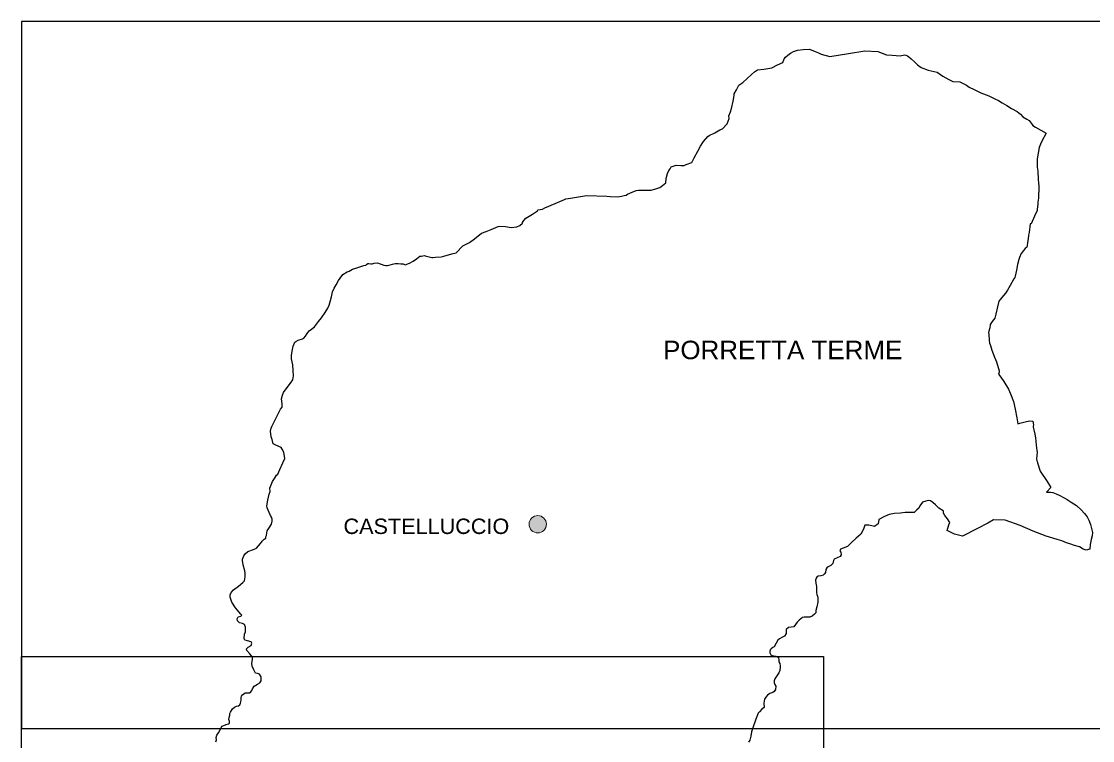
# Model space of a CAD drawing. Extents: x 645880 to 658994, y 884400 to 894744.
# Drawn here: x 646462 to 647332, y 885506 to 886090 of the extents above; entities that cross this region are included whole.
import ezdxf
from ezdxf.enums import TextEntityAlignment as Align

# ---------------------------------------------------------------- set-up
doc = ezdxf.new("R2010")
doc.units = 0
doc.header["$LTSCALE"] = 10
doc.layers.add('63', color=7, linetype='Continuous', lineweight=35)

msp = doc.modelspace()

# ---------------------------------------------------------------- hatches: boundary and pattern name
at = {"layer": '63'}
msp.add_hatch(color=256, dxfattribs=at).paths.add_polyline_path([(646888.14, 885681.98, 1), (646874.05, 885681.98, 1)])

# ---------------------------------------------------------------- linework, layer by layer
at = {"layer": '63', "lineweight": 25}
for points in [[(647342.83, 886090.07), (646461.84, 886090.07), (646461.84, 885516.07), (647342.83, 885516.07)], [(647342.83, 886090.07), (646461.84, 886090.07), (646461.84, 885516.07), (647342.83, 885516.07)], [(647113.21, 885058.94), (646461.84, 885058.94), (646461.84, 885574.51), (647113.21, 885574.51)]]:
    msp.add_lwpolyline(points, close=True, dxfattribs=at)
for points in [[(647034.9, 886007.04), (647036.53, 886011.16), (647036.21, 886013.32), (647037.56, 886016.62), (647038.28, 886019.32), (647039.79, 886025.24), (647040.58, 886029.86), (647040.58, 886031.25), (647042.4, 886034.66), (647044.38, 886038.35), (647047.64, 886040.43), (647054.7, 886047.12), (647057.08, 886049.28), (647059.54, 886050.82), (647064.61, 886051.43), (647069.61, 886052.2), (647071.2, 886052.51), (647075.72, 886054.82), (647080.12, 886056.72), (647081.23, 886059.65), (647082.26, 886061.11), (647084.25, 886062.8), (647086.23, 886064.34), (647088.69, 886065.57), (647092.02, 886066.73), (647096.46, 886067.19), (647101.78, 886067.57), (647106.38, 886065.65), (647108.91, 886064.5), (647111.24, 886063.54), (647118.1, 886061.69), (647133.29, 886063.96), (647146.57, 886066.15), (647157.27, 886065.53), (647164.34, 886062.93), (647168.79, 886062.58), (647175.22, 886062.1), (647178.75, 886062.86), (647180.03, 886062.79), (647181.23, 886062.24)], [(647181.23, 886062.24), (647182.43, 886061.42), (647184.19, 886059.77), (647187.16, 886056.96), (647189.47, 886054.72), (647192.51, 886052.73), (647198.09, 886050.47), (647205.3, 886048.96), (647210.1, 886045.74), (647214.84, 886042.86), (647218.12, 886041.36), (647223.77, 886040.94), (647229.21, 886038.41), (647231.4, 886036.83), (647235.29, 886034.84), (647240.87, 886032.17), (647247.44, 886029.77), (647252.25, 886027.23), (647255.07, 886025.86), (647258.27, 886023.98), (647262.02, 886021.78), (647265.62, 886019.31), (647270.35, 886016.85), (647272.9, 886014.93), (647274.95, 886012.66), (647278.27, 886010.68), (647280.11, 886009.65), (647280.81, 886008.55), (647282.37, 886006.29), (647283.07, 886005.6), (647285.18, 886004.25), (647293.8, 885999.25), (647290.34, 885993.01), (647289.21, 885990.54), (647288.29, 885987.73), (647286.6, 885978.46), (647286.67, 885971.82), (647287.09, 885968.52), (647287.31, 885961.74), (647287.52, 885959.2)], [(646903.87, 885946.01), (646907.76, 885946.7), (646920.69, 885948.78), (646937.19, 885948.24), (646939.91, 885948.07), (646945.78, 885947.76), (646949.11, 885948.38), (646951.1, 885948.92), (646952.84, 885949), (646953.95, 885949.92), (646957.6, 885951.61), (646961.09, 885952.77), (646962.92, 885953.07), (646966.25, 885953.15), (646970.69, 885953.15), (646973.15, 885953.15), (646977.83, 885954.54), (646980.21, 885955.15), (646982.35, 885957), (646984.97, 885959), (646985.45, 885962.69), (646986.32, 885966.62), (646987.59, 885969.08), (646988.65, 885970.49), (646989.52, 885972.1), (646993.41, 885973.49), (646997.22, 885973.18), (646999.99, 885973.1), (647001.5, 885973.88), (647006.1, 885975.64), (647008.09, 885979.34), (647010.94, 885984.73), (647013.09, 885988.96), (647015.78, 885992.73), (647019.11, 885996.81), (647020.15, 885997.58), (647024.75, 885999.73), (647028.95, 886001.96), (647031.17, 886002.96), (647034.9, 886007.04)], [(647287.52, 885959.2), (647287.8, 885955.98), (647287.77, 885946.5), (647287.22, 885943.28), (647287.01, 885941.63), (647286.92, 885939.77), (647286.67, 885937.42), (647286.46, 885936.72), (647284.33, 885932.06), (647281.56, 885925.83), (647281.01, 885925.74), (647280.04, 885918.68), (647279.61, 885916.58), (647279.35, 885913.52), (647278.76, 885910.55), (647278.33, 885907.91), (647278.08, 885906.96), (647276.8, 885905.64), (647275.48, 885904.24), (647274.63, 885903.04), (647273.65, 885901.64), (647272.3, 885898.57), (647271.58, 885896.76), (647270.64, 885892.84), (647269.75, 885888.26), (647268.77, 885883.35), (647268.43, 885882.27), (647267.71, 885881.08), (647264.69, 885875.72), (647262.56, 885872.08), (647260.78, 885869.44), (647257.97, 885866.06), (647256.78, 885864.58), (647255.42, 885862.92), (647254.4, 885858.39), (647253.03, 885852.61), (647252.19, 885849.12), (647250.15, 885846.64), (647248.27, 885844.08), (647248.27, 885843.59)], [(646773.44, 885892.63), (646776.89, 885893.95), (646780.04, 885895.36), (646782.68, 885897.42), (646785.4, 885899.48), (646786.59, 885899.56), (646788.89, 885899.98), (646789.74, 885899.9), (646795.02, 885898.41), (646795.87, 885898.41), (646798.16, 885898.74), (646802.59, 885899.07), (646804.89, 885899.56), (646807.61, 885900.31), (646812.37, 885901.63), (646814.72, 885902.38), (646820.34, 885907.99), (646825.53, 885910.63), (646829.61, 885913.52), (646835.31, 885918.3), (646839.05, 885919.46), (646843.31, 885921.27), (646848.97, 885923.73), (646849.91, 885923.81), (646855.01, 885923.56), (646859.35, 885922.82), (646863.95, 885923.23), (646866.58, 885924.47), (646868.8, 885926.29), (646868.71, 885926.95), (646869.73, 885928.43), (646871.26, 885930.33), (646876.88, 885933.55), (646880.96, 885936.44), (646881.26, 885937.16), (646884.91, 885937.62), (646886.89, 885938.7), (646895.23, 885942.31), (646902.76, 885945.62), (646903.87, 885946.01)], [(646681.11, 885819.01), (646681.63, 885822.48), (646682.56, 885826.53), (646683.93, 885829.75), (646684.61, 885830.33), (646686.48, 885831.32), (646689.97, 885832.39), (646691.08, 885833.05), (646692.36, 885834.62), (646693.78, 885836.77), (646695.4, 885838.92), (646697.45, 885840.32), (646699.83, 885842.22), (646703.07, 885846.52), (646705.37, 885849.49), (646708.43, 885853.7), (646710.56, 885857.42), (646711.58, 885859.73), (646712.77, 885863.62), (646713.52, 885866.61), (646714.54, 885870.57), (646715.82, 885873.63), (646717.27, 885876.27), (646719.31, 885879.74), (646720.76, 885881.81), (646722.8, 885884.78), (646726.38, 885886.93), (646727.91, 885887.26), (646729.27, 885888.09), (646730.64, 885889.08), (646733.36, 885889.9), (646739.75, 885891.89), (646741.37, 885892.38), (646742.05, 885892.88), (646743.16, 885893.7), (646744.01, 885893.7), (646745.59, 885893.38), (646746.53, 885893.38), (646748.23, 885893.95), (646751.04, 885894.12)], [(646751.04, 885894.12), (646752.32, 885893.71), (646753.85, 885893.04), (646755.98, 885892.38), (646757.6, 885892.05), (646759.05, 885892.05), (646761.26, 885892.55), (646763.14, 885893.04), (646765.18, 885893.54), (646766.8, 885893.62), (646767.82, 885893.62), (646769.95, 885893.38), (646771.91, 885893.21), (646773.44, 885892.63)], [(647248.27, 885843.59), (647248.19, 885841.36), (647247.42, 885838.55), (647247.08, 885837.23), (647247.25, 885835.99), (647247.59, 885831.45), (647247.93, 885828.9), (647248.61, 885827), (647249.89, 885823.37), (647252.02, 885817.51), (647253.55, 885813.79), (647255.59, 885806.42), (647255.59, 885805.43), (647255.25, 885803.78), (647257.12, 885801.38), (647259.5, 885797.75), (647263.42, 885791.48), (647264.78, 885787.93), (647267.25, 885781.66), (647268.61, 885775.39), (647270.13, 885768.35), (647270.9, 885763.48), (647272.43, 885763.97), (647277.96, 885765.29), (647280.68, 885765.79), (647283.06, 885765.62), (647283.66, 885762.74), (647283.4, 885761.5), (647283.23, 885760.75), (647283.83, 885758.53), (647284.59, 885755.14), (647285.19, 885752.17), (647285.53, 885749.53), (647285.87, 885746.23), (647286.21, 885741.69), (647286.47, 885740.37), (647286.04, 885735.17), (647286.29, 885733.41), (647286.89, 885732.42), (647286.81, 885731.68)], [(646664.2, 885689.14), (646663.01, 885691.63), (646661.3, 885695.35), (646661.13, 885696.84), (646661.81, 885701.63), (646663.09, 885706.25), (646663.69, 885708.48), (646663.6, 885711.13), (646665.82, 885716.74), (646667.35, 885719.22), (646669.05, 885721.78), (646670.08, 885722.69), (646671.78, 885726.49), (646673.99, 885731.7), (646675.61, 885735.28), (646674.84, 885740.56), (646673.48, 885742.96), (646672.63, 885744.36), (646668.37, 885746.02), (646666.32, 885747.17), (646665.47, 885750.73), (646664.62, 885752.96), (646664.19, 885757.42), (646664.53, 885760.06), (646665.05, 885761.22), (646672.28, 885775.43), (646673.56, 885777.08), (646673.63, 885778.17), (646673.46, 885779.82), (646673.03, 885783.71), (646673.8, 885786.6), (646674.57, 885788.91), (646676.87, 885791.97), (646680.19, 885796.6), (646682.32, 885799.16), (646682.83, 885802.3), (646682.49, 885806.84), (646682.15, 885811.47), (646681.21, 885816.18), (646681.11, 885819.01)], [(647286.81, 885731.68), (647288.93, 885725.07), (647294.8, 885716.66), (647297.78, 885711.7), (647294.26, 885708.06), (647296.15, 885707.98), (647297.49, 885708.12), (647299.3, 885707.69), (647302.02, 885706.74), (647305.02, 885705.38), (647310.81, 885702.16), (647314.29, 885700.02), (647318.46, 885697.13), (647322.38, 885693.66), (647325, 885690.56), (647327.22, 885688), (647328.41, 885685.36), (647329.77, 885681.81), (647331.47, 885675.38), (647331.28, 885672.63), (647330.47, 885669.46), (647329.56, 885665.42), (647329.2, 885661.64), (647326.48, 885660.85), (647323.94, 885661.73), (647320.86, 885663.66), (647316.79, 885664.72), (647313.16, 885666.12), (647310.26, 885667), (647306.55, 885668.5), (647302.83, 885669.46), (647293.77, 885672.36), (647283.26, 885676.41), (647272.72, 885681.03), (647260.58, 885685.34), (647251.15, 885685.51), (647246.44, 885682.87), (647238.11, 885678.48), (647225.96, 885672.24), (647219.47, 885674.01)], [(647219.47, 885674.01), (647213.4, 885677), (647214.85, 885681.57), (647215.75, 885683.5), (647213.85, 885686.32), (647211.67, 885688.96), (647210.59, 885690.89), (647210.59, 885692.65), (647210.13, 885692.82), (647206.69, 885694.93), (647204.06, 885697.74), (647201.89, 885699.5), (647200.08, 885700.91), (647198.26, 885701.17), (647196.3, 885700.82), (647193.49, 885699.94), (647191.23, 885696.86), (647190.5, 885695.11), (647188.96, 885693.7), (647186.61, 885691.59), (647185.25, 885691.5), (647180.92, 885691.6), (647179.38, 885691.52), (647175.66, 885690.99), (647170.86, 885690.64), (647166.51, 885689.76), (647162.53, 885688.18), (647157.99, 885685.8), (647157.45, 885682.29), (647154.55, 885680.18), (647153.28, 885680.44), (647149.93, 885681.14), (647146.76, 885681.23), (647145.58, 885678.07), (647143.41, 885673.94), (647139.51, 885670.68), (647135.89, 885667.08), (647132.53, 885664), (647129, 885662.51), (647126.77, 885661.75)], [(646636.88, 885605.26), (646637.9, 885606.75), (646640.03, 885607.49), (646640.71, 885608.07), (646640.11, 885609.06), (646635.77, 885614.18), (646632.79, 885618.81), (646631.34, 885622.77), (646631.34, 885624.67), (646632.26, 885626.52), (646634.14, 885628.76), (646637.97, 885631.81), (646641.63, 885634.78), (646643.08, 885635.94), (646643.51, 885639.16), (646643.59, 885642.3), (646643.16, 885644.29), (646641.89, 885649.08), (646641.38, 885652.55), (646641.46, 885653.7), (646642.31, 885656.42), (646643.51, 885657.82), (646645.72, 885659.73), (646650.15, 885661.54), (646652.62, 885662.45), (646655.85, 885666.42), (646656.79, 885667.41), (646657.39, 885668.32), (646659.01, 885669.97), (646660.2, 885670.55), (646660.37, 885671.62), (646660.88, 885672.94), (646661.05, 885674.93), (646661.39, 885676.74), (646663.01, 885679.06), (646664.88, 885682.11), (646665.31, 885684.34), (646665.31, 885686), (646664.88, 885687.81), (646664.2, 885689.14)], [(647126.77, 885661.75), (647126.41, 885660.35), (647127.04, 885659.29), (647127.5, 885657.18), (647126.68, 885655.78), (647124.14, 885654.72), (647121.79, 885653.67), (647121.15, 885652.44), (647120.61, 885650.06), (647118.95, 885648.59), (647116.94, 885647.39), (647115.77, 885646.51), (647115.05, 885645.31), (647114.66, 885642.85), (647113.75, 885641.4), (647112.77, 885640.52), (647110.89, 885640.01), (647108.87, 885639.95), (647107.96, 885639.69), (647106.99, 885638.24), (647106.47, 885636.6), (647106.86, 885634.21), (647107.44, 885631.56), (647107.53, 885629.45), (647107.53, 885626.68), (647107.72, 885625.04), (647108.18, 885623.65), (647108.57, 885622.32), (647108.57, 885620.62), (647108.37, 885618.73), (647107.59, 885614.94), (647106.75, 885612.04), (647106.81, 885610.15), (647105.9, 885608.89), (647103.82, 885607.37), (647101.87, 885606.43), (647100.37, 885606.62), (647097.25, 885606.62), (647096.15, 885606.17), (647093.41, 885604.03)], [(646640.66, 885542.3), (646641.21, 885543.46), (646642.36, 885544.36), (646643.51, 885545.07), (646645.17, 885545.11), (646647.13, 885545.27), (646648.02, 885545.89), (646648.96, 885547.01), (646649.43, 885548.25), (646650.92, 885550.52), (646653.6, 885552.21), (646655.44, 885553.35), (646656.46, 885555), (646656.63, 885558.06), (646655.18, 885560.29), (646653.39, 885560.7), (646651.77, 885561.2), (646650.58, 885563.92), (646649.31, 885566.9), (646648.88, 885569.29), (646649.47, 885572.1), (646649.47, 885574.08), (646647.43, 885576.89), (646644.88, 885579.54), (646644.62, 885580.94), (646646.07, 885582.26), (646648.45, 885583.67), (646649.05, 885585.4), (646648.28, 885586.56), (646645.39, 885587.47), (646643.26, 885587.96), (646642.66, 885589.29), (646643, 885592.76), (646643.86, 885594.68), (646643.69, 885598.32), (646642.84, 885600.47), (646641.31, 885601.29), (646638.92, 885601.95), (646637.39, 885603.61), (646636.88, 885605.26)], [(647093.41, 885604.03), (647091.79, 885602.58), (647089.06, 885598.67), (647084.77, 885598.16), (647082.75, 885596.46), (647082.68, 885593.37), (647081.45, 885591.22), (647079.32, 885590.08), (647077.3, 885588.94), (647076.13, 885587.94), (647074.7, 885585.54), (647073.01, 885582.51), (647071.9, 885581.88), (647070.47, 885580.93), (647069.69, 885579.92), (647069.37, 885578.79), (647069.43, 885577.59), (647070.41, 885575.95), (647071.51, 885575.57), (647074.25, 885574.81), (647076.59, 885573.74), (647076.85, 885571.66), (647076.91, 885570.4), (647077.63, 885568.82), (647078.02, 885567.31), (647078.02, 885566.11), (647077.56, 885563.14), (647076.72, 885561.31), (647075.09, 885558.92), (647073.59, 885556.52), (647073.07, 885554.94), (647073.14, 885553.36), (647073.66, 885551.98), (647074.47, 885550.58), (647074.21, 885547.8), (647073.03, 885546.16), (647071.93, 885545.53), (647069.52, 885544.71), (647067.7, 885543.26), (647066.21, 885541.68)], [(646619.67, 885505.3), (646620.14, 885506.91), (646620.06, 885509.02), (646620.61, 885510.71), (646621.72, 885512.69), (646623.29, 885515.09), (646624.02, 885516.99), (646624.83, 885518.06), (646626.1, 885518.72), (646628.2, 885519.44), (646629.95, 885519.94), (646630.76, 885520.43), (646630.89, 885521.1), (646630.67, 885522.25), (646630.25, 885523.57), (646630.46, 885525.1), (646630.97, 885527.08), (646631.06, 885528.41), (646631.52, 885529.52), (646633.14, 885532.04), (646634.97, 885533.57), (646636.34, 885534.19), (646638.17, 885534.64), (646639.06, 885535.47), (646639.61, 885536.71), (646639.95, 885537.95), (646640.15, 885539.45), (646640.27, 885541.39), (646640.66, 885542.3)], [(647066.21, 885541.68), (647065.3, 885540.04), (647064.71, 885536.64), (647064.84, 885533.23), (647062.95, 885531.91), (647061, 885529.76), (647059.96, 885528.5), (647058.08, 885523.64), (647055.48, 885516.01), (647054.5, 885513.54), (647053.98, 885509.94), (647053.33, 885506.72), (647052.16, 885505.02)]]:
    msp.add_lwpolyline(points, dxfattribs=at)
at = {"layer": '63', "lineweight": 13}
msp.add_circle((646881.09, 885681.98), 7.04, dxfattribs=at)

# ---------------------------------------------------------------- texts
at = {"layer": '63', "width": 1.05}
for s, height, p in [('PORRETTA TERME', 15, (647079.95, 885815.93)), ('CASTELLUCCIO', 12.5, (646790.65, 885674.06))]:
    msp.add_text(s, height=height, dxfattribs=at).set_placement(p, align=Align.CENTER)

doc.saveas('drawing.dxf')
